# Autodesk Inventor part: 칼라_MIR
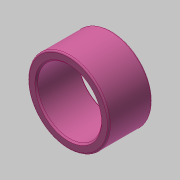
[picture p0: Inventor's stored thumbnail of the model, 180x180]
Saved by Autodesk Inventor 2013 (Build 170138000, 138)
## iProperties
Created: 2019-05
Part Number: 칼라_MIR
Material: 스테인리스강
Document SubType Name: Modeling
Designer: user
Density: 8.08 g/cm^3
Author: mduedu
d0: 22.000 mm
d1: 28.000 mm
d2: 15.000 mm
d3: 0.00 deg
d4: 0.500 mm
d5: 0.500 mm
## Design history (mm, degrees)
derived "칼라.ipt"
  sketch "스케치1"
    geometry: C1 r 11 at (0, 0) reference; C2 r 14 at (0, 0) reference; 1 further point
feature "솔리드1::칼라.ipt"
tag "피쳐 태그1"
node "솔리드1"
other parameters: "d0" = 10, "d0_1" = 22, "d1" = 28, "d2" = 15, "d3" = 0 deg, "d4" = 0.5, "d5" = 0.5
